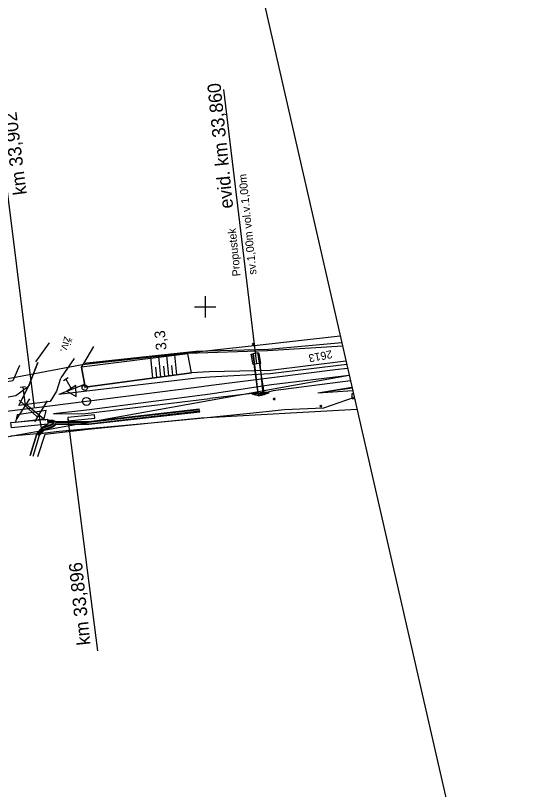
# Model space of a CAD drawing. Extents: x -805730 to -804640, y -1150889 to -1150366.
# Drawn here: x -804735.5 to -804640.4, y -1150590.3 to -1150445.4 of the extents above; entities that cross this region are included whole.
import ezdxf

# ---------------------------------------------------------------- set-up
doc = ezdxf.new("R2010")
doc.units = 0
for name, color, linetype in [('0381KM032-037P - Vrstva 1', 7, 'Continuous'), ('0381KM032-037P - Vrstva 13', 7, 'Continuous'), ('0381KM032-037P - Vrstva 17', 7, 'Continuous'), ('0381KM032-037P - Vrstva 19', 7, 'Continuous'), ('0381KM032-037P - Vrstva 25', 7, 'Continuous'), ('0381KM032-037P - Vrstva 4', 7, 'Continuous'), ('0381KM032-037P - Vrstva 43', 7, 'Continuous'), ('0381KM032-037P - Vrstva 48', 7, 'Continuous'), ('0381KM032-037P - Vrstva 49', 7, 'Continuous'), ('0381KM032-037P - Vrstva 51', 7, 'Continuous'), ('0381KM032-037P - Vrstva 57', 7, 'Continuous'), ('0381KM032-037P - Vrstva 7', 7, 'Continuous'), ('0381KM032-037P - Vrstva 9', 7, 'Continuous'), ('formát', 7, 'Continuous'), ('hran DP - hran DP', 7, 'Continuous'), ('krizky_1000 - Vrstva 1', 7, 'Continuous'), ('vyt_sit - polygon', 7, 'Continuous')]:
    doc.layers.add(name, color=color, linetype=linetype)

msp = doc.modelspace()

# ---------------------------------------------------------------- linework, layer by layer
at = {"layer": '0381KM032-037P - Vrstva 1'}
msp.add_lwpolyline([(-804673.35, -1150511.49), (-804675.7, -1150511.78), (-804698.85, -1150514.71), (-804701.61, -1150515.06), (-804722.18, -1150517.67), (-804729.05, -1150518.54), (-804735.1, -1150519.31), (-804744.56, -1150520.5), (-804767.65, -1150523.46), (-804791, -1150526.42)], dxfattribs=at)
at = {"layer": '0381KM032-037P - Vrstva 13'}
for points in [[(-804703.22, -1150508.8), (-804723.12, -1150511.26), (-804722.46, -1150514.99), (-804702.53, -1150512.35), (-804703.22, -1150508.8)], [(-804732.2, -1150527.92), (-804730.97, -1150524.01), (-804730.13, -1150523.06), (-804728.33, -1150522.36), (-804727.9, -1150521.95), (-804721.78, -1150521.96), (-804701.01, -1150519.63), (-804701.03, -1150519.46), (-804701.1, -1150519.22), (-804701.1, -1150519.05)], [(-804731.12, -1150523.92), (-804730.21, -1150522.94), (-804728.39, -1150522.25), (-804727.91, -1150521.81), (-804721.79, -1150521.85), (-804701.03, -1150519.46)], [(-804729.45, -1150521.32), (-804728.46, -1150521.31), (-804727.91, -1150521.54), (-804721.8, -1150521.59), (-804701.1, -1150519.22)], [(-804729.38, -1150521.22), (-804728.48, -1150521.2), (-804727.92, -1150521.41), (-804721.8, -1150521.43), (-804701.1, -1150519.05)], [(-804732.74, -1150527.78), (-804731.51, -1150523.73), (-804730.41, -1150522.51), (-804728.49, -1150521.85), (-804728.25, -1150521.76), (-804728.53, -1150521.71), (-804729.44, -1150521.68)], [(-804731.32, -1150523.78), (-804730.35, -1150522.68), (-804728.48, -1150521.99), (-804728.25, -1150521.76), (-804728.5, -1150521.58), (-804729.42, -1150521.57)], [(-804729.38, -1150521.22), (-804729.45, -1150521.32), (-804729.42, -1150521.57), (-804729.44, -1150521.68)], [(-804731.51, -1150523.73), (-804731.32, -1150523.78), (-804731.12, -1150523.92), (-804730.97, -1150524.01)]]:
    msp.add_lwpolyline(points, dxfattribs=at)
at = {"layer": '0381KM032-037P - Vrstva 17'}
for p, q in [((-804731.66, -1150510.27), (-804729.1, -1150506.73)), ((-804726.96, -1150513.28), (-804724.46, -1150509.62))]:
    msp.add_line(p, q, dxfattribs=at)
for points in [[(-804674.43, -1150506.74), (-804688.14, -1150507.97), (-804701.71, -1150508.32), (-804722.68, -1150510.59), (-804720.85, -1150507.4)], [(-804734.71, -1150510.96), (-804735.96, -1150513.84), (-804741.77, -1150514.83), (-804760.36, -1150517.2), (-804795.4, -1150521.06), (-804816.51, -1150523.78), (-804835.4, -1150526.88), (-804850, -1150530.66), (-804863.08, -1150534.36), (-804866.23, -1150530.55), (-804868.05, -1150528.28)], [(-804731.29, -1150527.98), (-804729.95, -1150523.81), (-804721.9, -1150522.89), (-804700.75, -1150520.73), (-804671.6, -1150519.14)]]:
    msp.add_lwpolyline(points, dxfattribs=at)
at = {"layer": '0381KM032-037P - Vrstva 19'}
for p, q in [((-804690.3, -1150510.66), (-804696.47, -1150459.27)), ((-804690.02, -1150516.61), (-804690.96, -1150508.7)), ((-804688.92, -1150516.37), (-804690.16, -1150508.54)), ((-804690.09, -1150516.25), (-804690.83, -1150510.72)), ((-804689.77, -1150510.59), (-804689.19, -1150516.28)), ((-804690.02, -1150516.61), (-804688.92, -1150516.37))]:
    msp.add_line(p, q, dxfattribs=at)
for points in [[(-804691.12, -1150508.86), (-804690.96, -1150508.7), (-804690.59, -1150508.62), (-804690.16, -1150508.54), (-804690.08, -1150508.63)], [(-804689.58, -1150510.57), (-804689.88, -1150508.68), (-804690.08, -1150508.63), (-804689.77, -1150510.59)], [(-804689.58, -1150510.57), (-804689.77, -1150510.59), (-804690.83, -1150510.72), (-804691.04, -1150510.74), (-804691.4, -1150508.85), (-804691.12, -1150508.86), (-804690.83, -1150510.72)], [(-804688.16, -1150516.11), (-804688.92, -1150516.37), (-804689.19, -1150516.28), (-804690.09, -1150516.25), (-804690.02, -1150516.61), (-804691.14, -1150516.38)]]:
    msp.add_lwpolyline(points, dxfattribs=at)
msp.add_lwpolyline([(-804688.22, -1150515.92), (-804688.16, -1150516.11), (-804691.14, -1150516.38), (-804691.19, -1150516.18)], close=True, dxfattribs=at)
at = {"layer": '0381KM032-037P - Vrstva 25'}
for points in [[(-804672.5, -1150517.17), (-804672.5, -1150516.17), (-804672.27, -1150516.17)], [(-804672.05, -1150517.17), (-804672.5, -1150517.17)]]:
    msp.add_lwpolyline(points, dxfattribs=at)
at = {"layer": '0381KM032-037P - Vrstva 4'}
for p, q in [((-804738.68, -1150465.82), (-804731.99, -1150518.9)), ((-804699.22, -1150512.12), (-804702.53, -1150512.35)), ((-804733.62, -1150514.94), (-804734.61, -1150515.06)), ((-804734.11, -1150515), (-804733.68, -1150518.47)), ((-804688.22, -1150515.92), (-804691.19, -1150516.18)), ((-804732.83, -1150517.21), (-804735.37, -1150521.05)), ((-804731.4, -1150520.55), (-804734.81, -1150517.46)), ((-804691.19, -1150516.18), (-804699.14, -1150517.12)), ((-804729.05, -1150518.54), (-804735.1, -1150519.31)), ((-804733.43, -1150518.25), (-804729.87, -1150521.17)), ((-804731.84, -1150521.52), (-804729.49, -1150517.55)), ((-804730.44, -1150523.66), (-804731.05, -1150520.21)), ((-804730.93, -1150523.75), (-804729.95, -1150523.57))]:
    msp.add_line(p, q, dxfattribs=at)
for points in [[(-804673.66, -1150510.13), (-804687.8, -1150511.91), (-804699.22, -1150512.12)], [(-804673.51, -1150510.75), (-804687.82, -1150512.54), (-804699.1, -1150513.12)], [(-804702.53, -1150512.35), (-804722.46, -1150514.99), (-804722.57, -1150514.49)], [(-804673.03, -1150512.84), (-804687.61, -1150514.59), (-804699.07, -1150516.32)], [(-804699.1, -1150513.12), (-804701.6, -1150513.32), (-804727.4, -1150516.37)], [(-804722.57, -1150514.49), (-804727.4, -1150516.37)], [(-804672.81, -1150513.82), (-804687.3, -1150515.71), (-804688.22, -1150515.92)], [(-804699.07, -1150516.32), (-804722.12, -1150519.29), (-804728.4, -1150520.02), (-804722.36, -1150519.97), (-804699.14, -1150517.12)]]:
    msp.add_lwpolyline(points, dxfattribs=at)
at = {"layer": '0381KM032-037P - Vrstva 43'}
msp.add_lwpolyline([(-804736.33, -1150521.65), (-804729.5, -1150520.98), (-804729.45, -1150521.92), (-804736.22, -1150522.62)], close=True, dxfattribs=at)
at = {"layer": '0381KM032-037P - Vrstva 48'}
for p, q in [((-804709.78, -1150513.31), (-804710.17, -1150509.4)), ((-804708.29, -1150513.12), (-804708.68, -1150509.26)), ((-804706.81, -1150512.92), (-804707.19, -1150509.11)), ((-804705.32, -1150512.72), (-804705.69, -1150508.97)), ((-804709.04, -1150513.21), (-804709.23, -1150511.27)), ((-804707.55, -1150513.02), (-804707.74, -1150511.1)), ((-804706.06, -1150512.82), (-804706.25, -1150510.93))]:
    msp.add_line(p, q, dxfattribs=at)
at = {"layer": '0381KM032-037P - Vrstva 49'}
for p, q in [((-804690.87, -1150506.79), (-804691.22, -1150507.14)), ((-804691.22, -1150506.79), (-804690.87, -1150507.14)), ((-804686.9, -1150517.05), (-804687.25, -1150517.41)), ((-804687.25, -1150517.05), (-804686.9, -1150517.41)), ((-804678.19, -1150518.41), (-804678.54, -1150518.76)), ((-804678.54, -1150518.41), (-804678.19, -1150518.76))]:
    msp.add_line(p, q, dxfattribs=at)
for points in [[(-804674.3, -1150507.31), (-804688.31, -1150508.22), (-804703.24, -1150508.74), (-804722.68, -1150510.59)], [(-804673.66, -1150510.13), (-804687.8, -1150511.91), (-804699.22, -1150512.12)], [(-804731.33, -1150510.42), (-804733.06, -1150514.89), (-804735.43, -1150516.61), (-804744.9, -1150518.34), (-804767.83, -1150521.26), (-804795.17, -1150523.55), (-804815.65, -1150527.19), (-804834.76, -1150530), (-804839.27, -1150531.31), (-804861.98, -1150536.58)], [(-804722.46, -1150514.99), (-804723.12, -1150511.26), (-804722.68, -1150510.59)], [(-804699.22, -1150512.12), (-804702.53, -1150512.35), (-804722.46, -1150514.99)], [(-804672.53, -1150515.06), (-804678.92, -1150516.15)], [(-804672.49, -1150515.21), (-804675.11, -1150515.57), (-804678.92, -1150516.15)], [(-804672.38, -1150515.72), (-804678.92, -1150516.15)], [(-804690.02, -1150516.61), (-804688.92, -1150516.37), (-804689.47, -1150516.35), (-804690.02, -1150516.61)]]:
    msp.add_lwpolyline(points, dxfattribs=at)
at = {"layer": '0381KM032-037P - Vrstva 51'}
msp.add_line((-804725.64, -1150513.28), (-804726.5, -1150513.8), dxfattribs=at)
for points in [[(-804727.06, -1150513.38), (-804727.78, -1150515.77), (-804729, -1150517.7), (-804734.83, -1150518.42), (-804733.06, -1150514.89), (-804731.33, -1150510.42)], [(-804726.07, -1150513.54), (-804725.04, -1150515.25), (-804725.9, -1150515.77), (-804724.14, -1150516.75), (-804724.18, -1150514.73), (-804725.04, -1150515.25)], [(-804729.45, -1150521.92), (-804730.41, -1150522.51), (-804731.51, -1150523.73), (-804732.74, -1150527.78)]]:
    msp.add_lwpolyline(points, dxfattribs=at)
msp.add_lwpolyline([(-804730.11, -1150520.97), (-804729.76, -1150519.41), (-804735.16, -1150520.17), (-804735.48, -1150521.58)], close=True, dxfattribs=at)
at = {"layer": '0381KM032-037P - Vrstva 7'}
msp.add_line((-804722.48, -1150515.11), (-804722.58, -1150515.12), dxfattribs=at)
for centre, radius in [((-804722.53, -1150515.12), 0.5), ((-804722.2, -1150517.67), 0.75)]:
    msp.add_circle(centre, radius, dxfattribs=at)
at = {"layer": '0381KM032-037P - Vrstva 9'}
for p, q in [((-804720.72, -1150520.2), (-804725.69, -1150520.71)), ((-804720.66, -1150520.79), (-804720.72, -1150520.2)), ((-804725.69, -1150520.71), (-804725.63, -1150521.31)), ((-804725.66, -1150521.01), (-804720.15, -1150564.39)), ((-804725.63, -1150521.31), (-804720.66, -1150520.79)), ((-804725.63, -1150521.31), (-804725.57, -1150521.9))]:
    msp.add_line(p, q, dxfattribs=at)
at = {"layer": 'formát'}
msp.add_line((-804706.6, -1150365.97), (-804640.43, -1150655.5), dxfattribs=at)
at = {"layer": 'hran DP - hran DP'}
for p, q in [((-804688.55, -1150506.95), (-804674.73, -1150505.41)), ((-804723.03, -1150510.78), (-804688.55, -1150506.95)), ((-804747.72, -1150515.43), (-804723.03, -1150510.78)), ((-804672.1, -1150516.95), (-804677.85, -1150518.93)), ((-804688.56, -1150519.6), (-804700.23, -1150520.83)), ((-804685.22, -1150519.25), (-804688.56, -1150519.6)), ((-804677.85, -1150518.93), (-804685.22, -1150519.25)), ((-804700.23, -1150520.83), (-804710.79, -1150521.81)), ((-804710.79, -1150521.81), (-804727.28, -1150523.34)), ((-804729.97, -1150523.63), (-804736.36, -1150524.18)), ((-804727.28, -1150523.34), (-804729.97, -1150523.63))]:
    msp.add_line(p, q, dxfattribs=at)
at = {"layer": 'krizky_1000 - Vrstva 1'}
for points in [[(-804700, -1150498), (-804700, -1150502)], [(-804702, -1150500), (-804698, -1150500)]]:
    msp.add_lwpolyline(points, dxfattribs=at)
at = {"layer": 'vyt_sit - polygon'}
msp.add_line((-804740.83, -1150524.99), (-804673.06, -1150512.75), dxfattribs=at)

# ---------------------------------------------------------------- texts
at = {"layer": '0381KM032-037P - Vrstva 19'}
for s, height, p in [('evid. km 33,860', 2.5, (-804694.74, -1150481.46)), ('sv.1,00m vol.v.1,00m', 1.5, (-804690.37, -1150493.89)), ('Propustek', 1.5, (-804693.36, -1150494.19))]:
    msp.add_text(s, height=height, rotation=95.8316, dxfattribs=at).set_placement(p)
at = {"layer": '0381KM032-037P - Vrstva 4'}
msp.add_text('km 33,902', height=2.5, rotation=97.1938, dxfattribs=at).set_placement((-804733.36, -1150478.88))
at = {"layer": '0381KM032-037P - Vrstva 48'}
msp.add_text('3,3', height=2, rotation=95.4373, dxfattribs=at).set_placement((-804707.19, -1150508.01))
at = {"layer": '0381KM032-037P - Vrstva 51'}
msp.add_text('živ.', height=1.5, rotation=253.3622, dxfattribs=at).set_placement((-804726.29, -1150505.42))
at = {"layer": '0381KM032-037P - Vrstva 57'}
msp.add_text('2613', height=1.5, rotation=191.1139, dxfattribs=at).set_placement((-804676.37, -1150508.07))
at = {"layer": '0381KM032-037P - Vrstva 9'}
msp.add_text('km 33,896', height=2.5, rotation=95.8904, dxfattribs=at).set_placement((-804721.45, -1150563.2))

doc.saveas('drawing.dxf')
